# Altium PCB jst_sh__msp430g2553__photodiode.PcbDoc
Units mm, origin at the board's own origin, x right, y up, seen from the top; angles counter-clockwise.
Board outline 56 x 30 mm, 2 copper layers (Top, Bottom), stack 0 mm thick; 17 components, 9 nets, 65 pads, 24 vias.
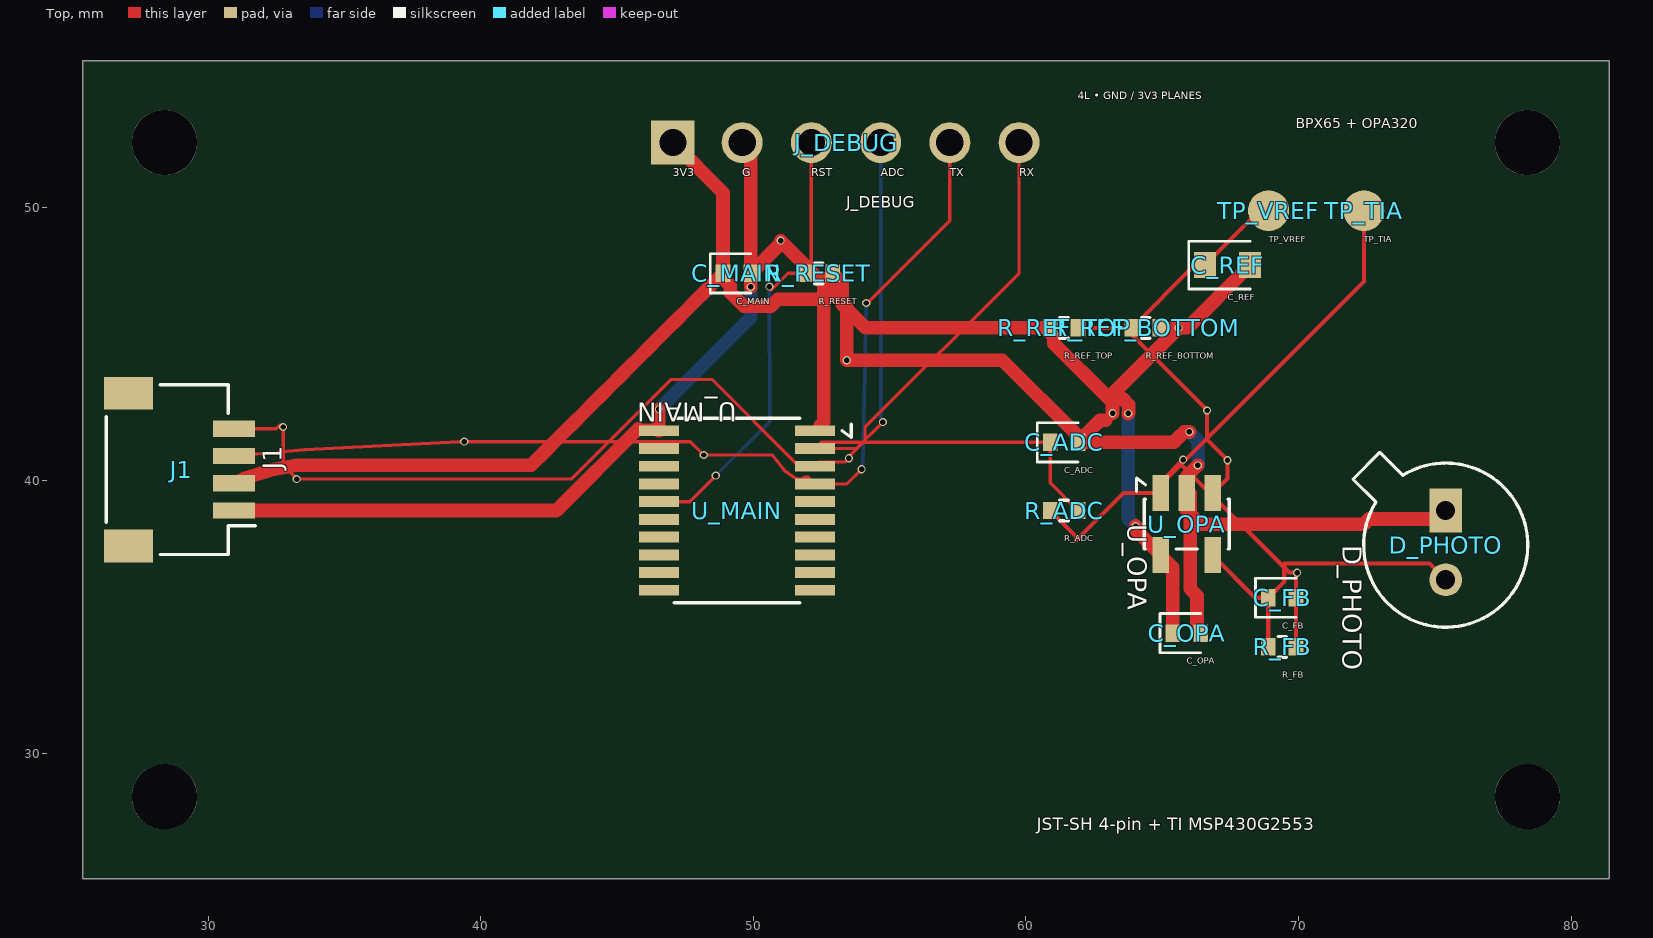
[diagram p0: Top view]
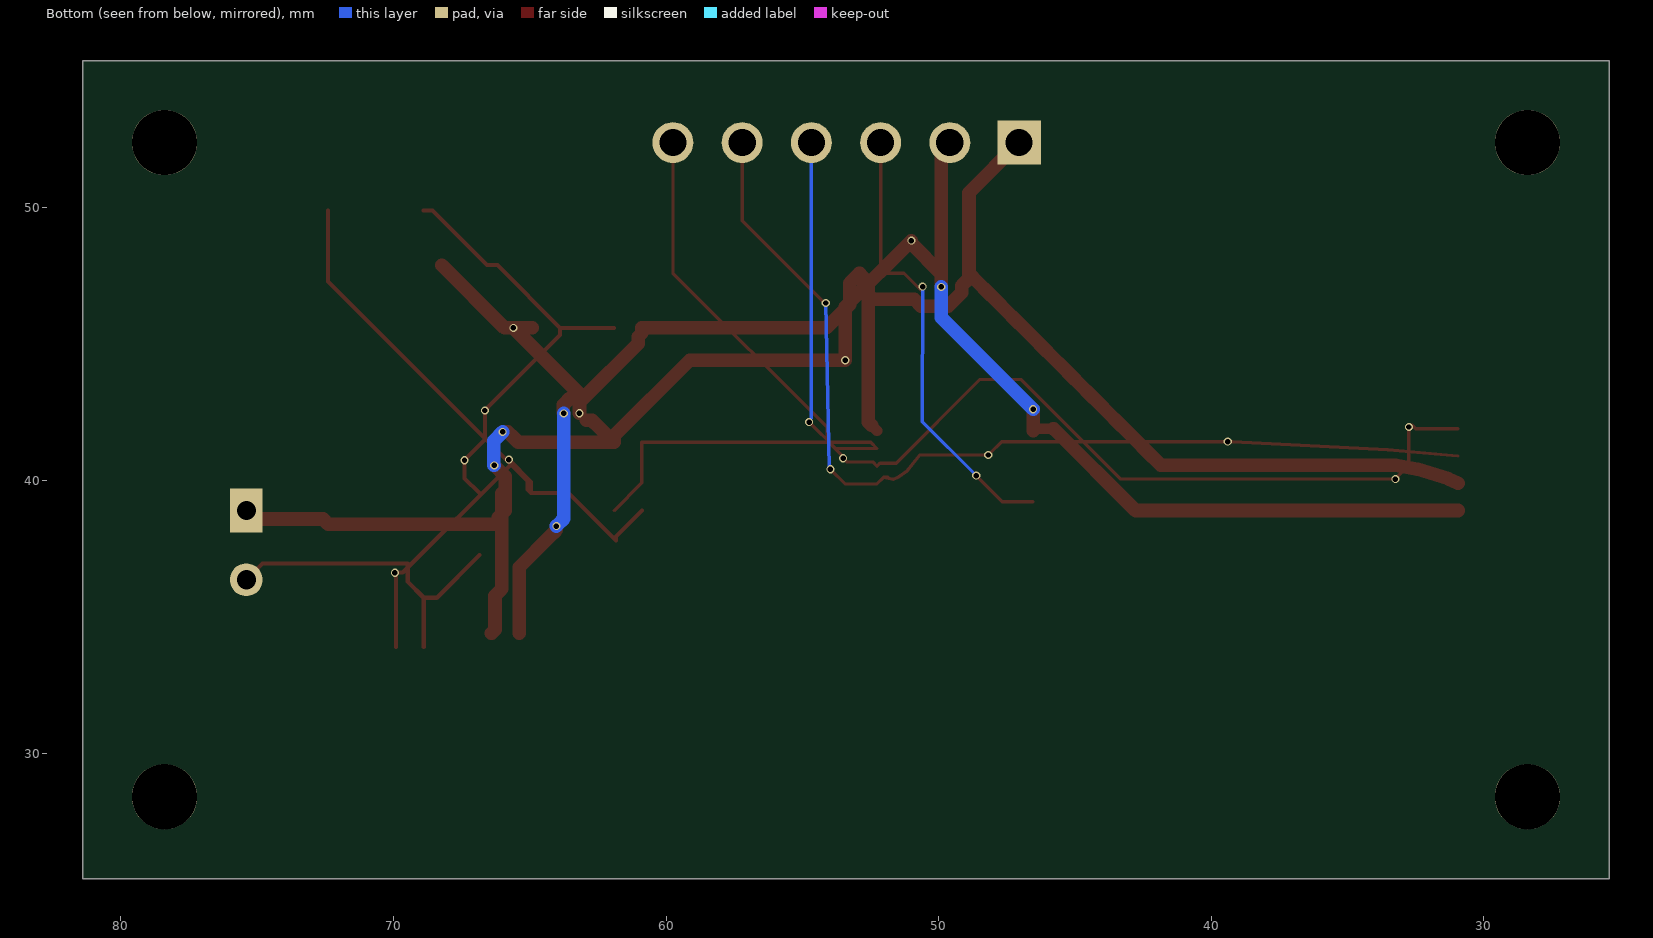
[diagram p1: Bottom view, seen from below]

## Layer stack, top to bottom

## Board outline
25.4,55.4 81.4,55.4 81.4,25.4 25.4,25.4

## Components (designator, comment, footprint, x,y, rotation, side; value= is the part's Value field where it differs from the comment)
C_ADC "" TSCIRCUIT-1.5600x0.6400mm 61.4,41.4 r0 top
C_FB "" TSCIRCUIT-1.5600x0.6400mm 69.4,35.7 r0 top
C_MAIN "" TSCIRCUIT-1.5600x0.6400mm 49.4,47.6 r0 top
C_OPA "" TSCIRCUIT-1.5600x0.6400mm 65.9,34.4 r0 top
C_REF "" TSCIRCUIT-2.4500x0.9500mm 67.4,47.9 r0 top
D_PHOTO "" TSCIRCUIT-1.2000x3.9400mm 75.4,37.73 r270 top
J1 "" TSCIRCUIT-5.5500x6.8000mm 28.95,40.4 r90 top
J_DEBUG "" TSCIRCUIT-14.2000x1.5000mm 53.4,52.4 r0 top
R_ADC "" TSCIRCUIT-1.5600x0.6400mm 61.4,38.9 r0 top
R_FB "" TSCIRCUIT-1.5600x0.6400mm 69.4,33.9 r0 top
R_REF_BOTTOM "" TSCIRCUIT-1.5600x0.6400mm 64.4,45.6 r0 top
R_REF_TOP "" TSCIRCUIT-1.5600x0.6400mm 61.4,45.6 r0 top
R_RESET "" TSCIRCUIT-1.5600x0.6400mm 52.4,47.6 r0 top
TP_TIA "" TSCIRCUIT-1.5000x1.5000mm 72.4,49.9 r0 top
TP_VREF "" TSCIRCUIT-1.5000x1.5000mm 68.9,49.9 r0 top
U_MAIN "" TSCIRCUIT-7.2000x6.2500mm 49.4,38.9 r180 top
U_OPA "" TSCIRCUIT-2.5000x3.6000mm 65.9,38.4 r270 top

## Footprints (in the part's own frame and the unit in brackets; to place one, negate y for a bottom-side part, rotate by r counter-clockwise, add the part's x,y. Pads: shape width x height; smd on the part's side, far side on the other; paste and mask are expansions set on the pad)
TSCIRCUIT-1.2000x3.9400mm [mm]
  rect 1.6x1.2 hole 0.7: 1(-1.17,0)
  round 1.2 hole 0.7: 2(1.37,0)
  silkscreen extent -3.3,-3.4 3.11,3.01
TSCIRCUIT-1.5000x1.5000mm [mm]
  round 1.5 smd: 1(0,0)
TSCIRCUIT-1.5600x0.6400mm [mm]
  rect 0.54x0.64 smd: 1(-0.51,0) 2(0.51,0)
  silkscreen extent -0.98,-0.72 0.51,0.72
TSCIRCUIT-2.4500x0.9500mm [mm]
  rect 0.8x0.95 smd: 1(-0.825,0) 2(0.825,0)
  silkscreen extent -1.43,-0.87 0.82,0.87
TSCIRCUIT-2.5000x3.6000mm [mm]
  rect 1.325x0.6 smd: 1(-1.138,-0.95) 2(-1.138,0) 3(-1.138,0.95) 4(1.137,0.95) 5(1.137,-0.95)
  silkscreen extent -1.69,-1.84 0.91,1.56
TSCIRCUIT-5.5500x6.8000mm [mm]
  rect 1.2x1.8 smd: 1(-2.8,1.875) 1(2.8,1.875)
  rect 0.6x1.55 smd: 1(-1.5,-2) 2(-0.5,-2) 3(0.5,-2) 4(1.5,-2)
  silkscreen extent -3.11,-2.77 3.11,2.69
TSCIRCUIT-7.2000x6.2500mm [mm]
  rect 1.475x0.4 smd: 1(-2.862,-2.925) 2(-2.862,-2.275) 3(-2.862,-1.625) 4(-2.862,-0.975) 5(-2.862,-0.325) 6(-2.862,0.325) 7(-2.862,0.975) 8(-2.862,1.625) 9(-2.862,2.275) 10(-2.862,2.925) 11(2.863,2.925) 12(2.863,2.275) 13(2.863,1.625) 14(2.863,0.975) 15(2.863,0.325) 16(2.863,-0.325) 17(2.863,-0.975) 18(2.863,-1.625) 19(2.863,-2.275) 20(2.863,-2.925)
  silkscreen extent -4.19,-3.38 2.31,3.39
TSCIRCUIT-14.2000x1.5000mm [mm]
  rect 1.6x1.6 hole 1: 1(-6.35,0)
  round 1.5 hole 1: 2(-3.81,0) 3(-1.27,0) 4(1.27,0) 5(3.81,0) 6(6.35,0)

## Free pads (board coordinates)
  round 2.4 hole 2.4 unplated: NPTH-1(28.4,28.4) NPTH-2(78.4,52.4) NPTH-3(78.4,28.4) NPTH-4(28.4,52.4)

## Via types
v1: diameter 0.3, hole 0.2, Top to Bottom, 24 vias

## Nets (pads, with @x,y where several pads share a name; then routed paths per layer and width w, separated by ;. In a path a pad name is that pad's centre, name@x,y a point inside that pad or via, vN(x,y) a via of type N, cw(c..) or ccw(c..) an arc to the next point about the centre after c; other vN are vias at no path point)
ADC_IN: C_ADC.1 J_DEBUG.4 R_ADC.2 U_MAIN.2 | length 24.8
  Top w0.12: v1(54.755,42.146) 53.784,41.175 U_MAIN.2 52.487,41.4 C_ADC.1 60.89,39.92 R_ADC.2
  Bottom w0.12: J_DEBUG.4 54.67,42.283 54.764,42.189 54.764,42.155 v1(54.755,42.146)
GND: C_ADC.2 C_MAIN.2 C_OPA.2 C_REF.2 D_PHOTO.1 J1.1@30.95,38.9 J_DEBUG.2 R_REF_BOTTOM.2 U_MAIN.20 U_OPA.2 | length 79.6
  Top w0.35: 62.919,42.207 v1(63.179,42.467)
  Top w0.4: U_MAIN.20@45.8,41.9 46.463,41.9 U_MAIN.20
  Top w0.5: J1.1@30.95,38.9 31.446,38.9 31.943,38.9 32.439,38.9 32.936,38.9 33.432,38.9 33.928,38.9 34.425,38.9 34.921,38.9 35.417,38.9 35.914,38.9 36.41,38.9 36.907,38.9 37.403,38.9 42.775,38.9 45.775,41.9 U_MAIN.20@45.8,41.9 ; v1(46.536,42.613) 46.536,41.827 U_MAIN.20 ; J_DEBUG.2 49.91,52.08 C_MAIN.2 ; v1(49.903,47.103) 49.91,47.11 C_MAIN.2 ; 62.919,42.207 62.717,42.207 62.448,41.938 62.179,41.669 C_ADC.2 ; v1(63.179,42.467) 63.179,43.179 v1(65.6,45.6) 65.41,45.6 R_REF_BOTTOM.2 65.925,45.6 C_REF.2 ; v1(65.997,41.782) 65.988,41.791 65.808,41.791 65.612,41.595 65.417,41.4 64.978,41.4 64.54,41.4 64.102,41.4 63.663,41.4 63.225,41.4 62.787,41.4 62.348,41.4 C_ADC.2 ; v1(66.307,40.557) 65.9,40.15 U_OPA.2 ; C_OPA.2 66.4,34.4 66.275,34.525 66.275,35.775 66.025,36.025 66.025,39.525 65.912,39.525 U_OPA.2 ; D_PHOTO.1 75.089,38.589 74.611,38.589 74.134,38.589 73.657,38.589 73.18,38.589 72.703,38.589 72.589,38.589 72.4,38.4 66.15,38.4 66.15,38.65 65.9,38.9 U_OPA.2 ; C_MAIN.2 51.001,48.691 v1(51.001,48.8) 53.429,46.372 v1(53.429,44.415) 53.926,44.415 54.423,44.415 54.92,44.415 55.417,44.415 55.914,44.415 56.41,44.415 56.907,44.415 59.135,44.415 61.91,41.64 C_ADC.2
  Bottom w0.5: v1(46.536,42.613) 49.903,45.981 v1(49.903,47.103) ; v1(65.997,41.782) 66.317,41.462 66.317,41.064 66.317,40.666 66.317,40.567 v1(66.307,40.557)
MAIN_RESET: J_DEBUG.3 R_RESET.1 U_MAIN.16 | length 16.8
  Top w0.12: U_MAIN.16 47.665,39.225 v1(48.623,40.183) ; v1(50.588,47.114) 50.649,46.977 51.272,47.6 R_RESET.1 52.13,47.84 J_DEBUG.3
  Bottom w0.12: v1(48.623,40.183) 48.668,40.228 50.598,42.158 v1(50.588,47.114)
PD_SUM: C_FB.1 D_PHOTO.2 R_FB.1 U_OPA.4 | length 12.2
  Top w0.15: U_OPA.4 68.412,35.7 C_FB.1 ; R_FB.1 C_FB.1 ; D_PHOTO.2 74.804,36.956 69.479,36.96 69.479,36.289 C_FB.1
TIA_OUT: C_FB.2 R_ADC.1 R_FB.2 TP_TIA.1 U_OPA.1 | length 29.2
  Top w0.15: R_ADC.1 61.839,37.951 61.839,37.8 63.577,39.538 U_OPA.1 ; R_FB.2 C_FB.2 69.91,36.45 69.91,36.584 v1(69.95,36.619) 69.661,36.624 65.642,40.643 v1(65.766,40.767) 64.95,39.951 U_OPA.1 ; TP_TIA.1 72.4,47.296 65.085,39.981 65.085,39.672 U_OPA.1
UART_MAIN_RX: J1.4 J_DEBUG.6 U_MAIN.3 | length 41.4
  Top w0.12: J1.4 32.5,41.9 32.641,42.041 32.674,42.041 v1(32.751,41.964) 32.751,40.576 33.182,40.144 33.182,40.119 v1(33.246,40.055) 43.328,40.055 46.981,43.708 48.484,43.708 51.559,40.633 52.155,40.633 U_MAIN.3 52.42,40.683 52.446,40.683 53.373,40.683 v1(53.506,40.816) 53.562,40.872 53.562,40.924 54.094,41.456 54.094,41.953 59.75,47.609 J_DEBUG.6
UART_MAIN_TX: J1.3 J_DEBUG.5 U_MAIN.4 | length 37.7
  Top w0.12: J1.3 33.53,41.128 39.233,41.423 39.392,41.423 v1(39.396,41.427) 47.69,41.427 48.136,40.981 v1(48.181,40.936) 50.695,40.936 51.164,40.345 51.475,40.128 51.665,40.044 52.021,40.116 ; v1(53.974,40.412) 53.437,39.875 U_MAIN.4 52.021,40.116 ; v1(54.142,46.513) 54.089,46.46 54.141,46.46 57.21,49.529 J_DEBUG.5 ; 52.021,40.116 51.872,40.116 52.021,40.116
  Bottom w0.12: v1(53.974,40.412) 54.009,40.447 54.009,40.46 54.016,40.467 v1(54.142,46.513)
VCC_3V3: C_MAIN.1 C_OPA.1 J1.2 J_DEBUG.1 R_REF_TOP.1 R_RESET.2 U_MAIN.1 U_OPA.5 | length 60.8
  Top w0.4: U_MAIN.1 52.462,42.025
  Top w0.5: J1.2 31.308,40.067 32.438,40.419 33.233,40.567 41.857,40.567 42.393,41.103 42.735,41.445 43.077,41.787 43.419,42.129 43.761,42.471 44.103,42.813 44.445,43.155 44.787,43.497 45.129,43.839 45.471,44.181 45.813,44.523 46.155,44.865 46.496,45.206 46.838,45.548 47.18,45.89 47.522,46.232 47.864,46.574 48.206,46.916 48.548,47.258 C_MAIN.1 ; J_DEBUG.1 48.89,50.56 C_MAIN.1 ; 52.463,42.025 52.586,42.149 52.586,47.276 R_RESET.2 ; v1(63.755,42.46) 63.775,42.48 63.775,42.775 63.525,43.025 63.025,43.025 61.025,45.025 61.025,45.275 60.89,45.41 R_REF_TOP.1 54.123,45.6 53.266,46.457 53.266,47.244 R_RESET.2 ; v1(64.024,38.33) 64.024,38.188 64.333,37.88 64.641,37.571 U_OPA.5 65.39,36.822 C_OPA.1 ; C_MAIN.1 48.89,47.41 49.15,47.15 49.15,46.9 49.65,46.4 50.65,46.4 50.9,46.65 52.4,46.65 52.65,46.9 52.65,47.15 52.9,47.4 52.9,47.61 R_RESET.2
  Bottom w0.5: v1(63.755,42.46) 63.754,41.978 63.753,41.497 63.752,41.015 63.751,40.533 63.751,40.051 63.75,39.57 63.749,39.088 63.748,38.606 63.992,38.362 v1(64.024,38.33)
VREF_0V5: C_REF.1 R_REF_BOTTOM.1 R_REF_TOP.2 TP_VREF.1 U_OPA.3 | length 16.5
  Top w0.15: R_REF_TOP.2 R_REF_BOTTOM.1 ; U_OPA.3 67.395,40.082 v1(67.395,40.742) 67.31,40.827 67.31,40.845 66.647,41.507 v1(66.647,42.569) 66.527,42.689 66.527,42.695 63.89,45.332 R_REF_BOTTOM.1 ; TP_VREF.1 68.575,49.9 C_REF.1 66.19,47.9 R_REF_BOTTOM.1
pads on no net: J1.1@27.075,37.6 J1.1@27.075,43.2 U_MAIN.5 U_MAIN.6 U_MAIN.7 U_MAIN.8 U_MAIN.9 U_MAIN.10 U_MAIN.11 U_MAIN.12 U_MAIN.13 U_MAIN.14 U_MAIN.15 U_MAIN.17 U_MAIN.18 U_MAIN.19

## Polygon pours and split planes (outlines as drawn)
GND on Mid1 (solid): 81.1,55.1 25.7,55.1 25.7,25.7 81.1,25.7
VCC_3V3 on Mid2 (solid): 81.1,55.1 25.7,55.1 25.7,25.7 81.1,25.7

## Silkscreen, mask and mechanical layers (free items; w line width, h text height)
Top Overlay:
  text "4L • GND / 3V3 PLANES" at 61.9,53.9 h0.48
  text "BPX65 + OPA320" at 69.9,52.8 h0.65
  text "JST-SH 4-pin + TI MSP430G2553" at 60.4,27 h0.78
